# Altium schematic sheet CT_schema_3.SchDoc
size 578 x 363 mm
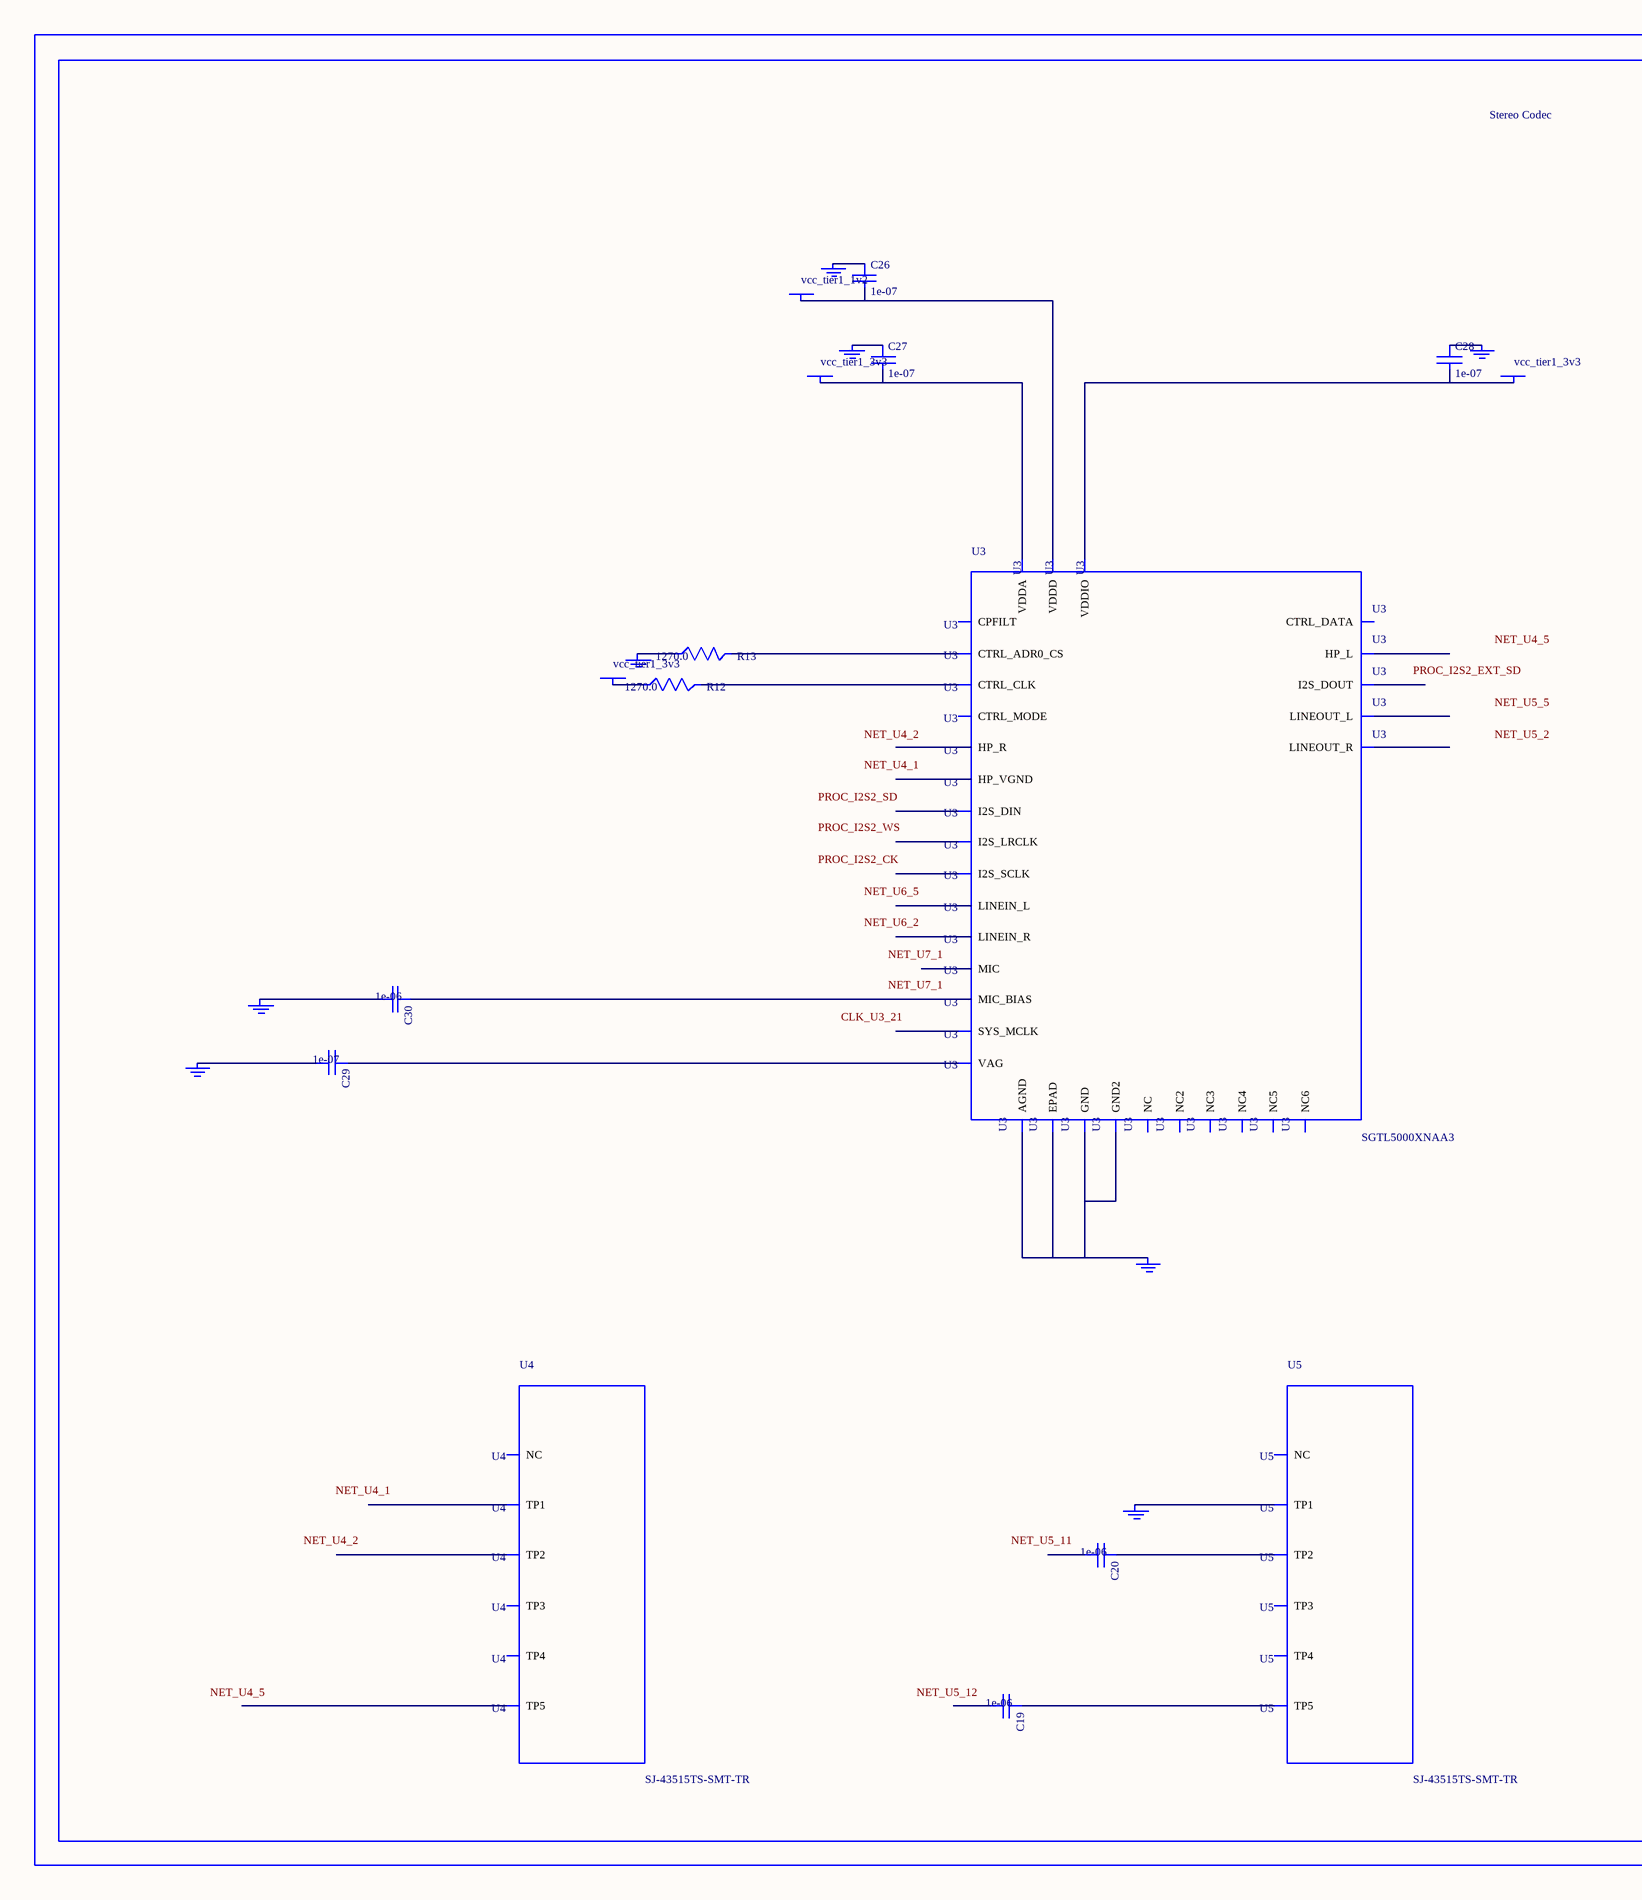
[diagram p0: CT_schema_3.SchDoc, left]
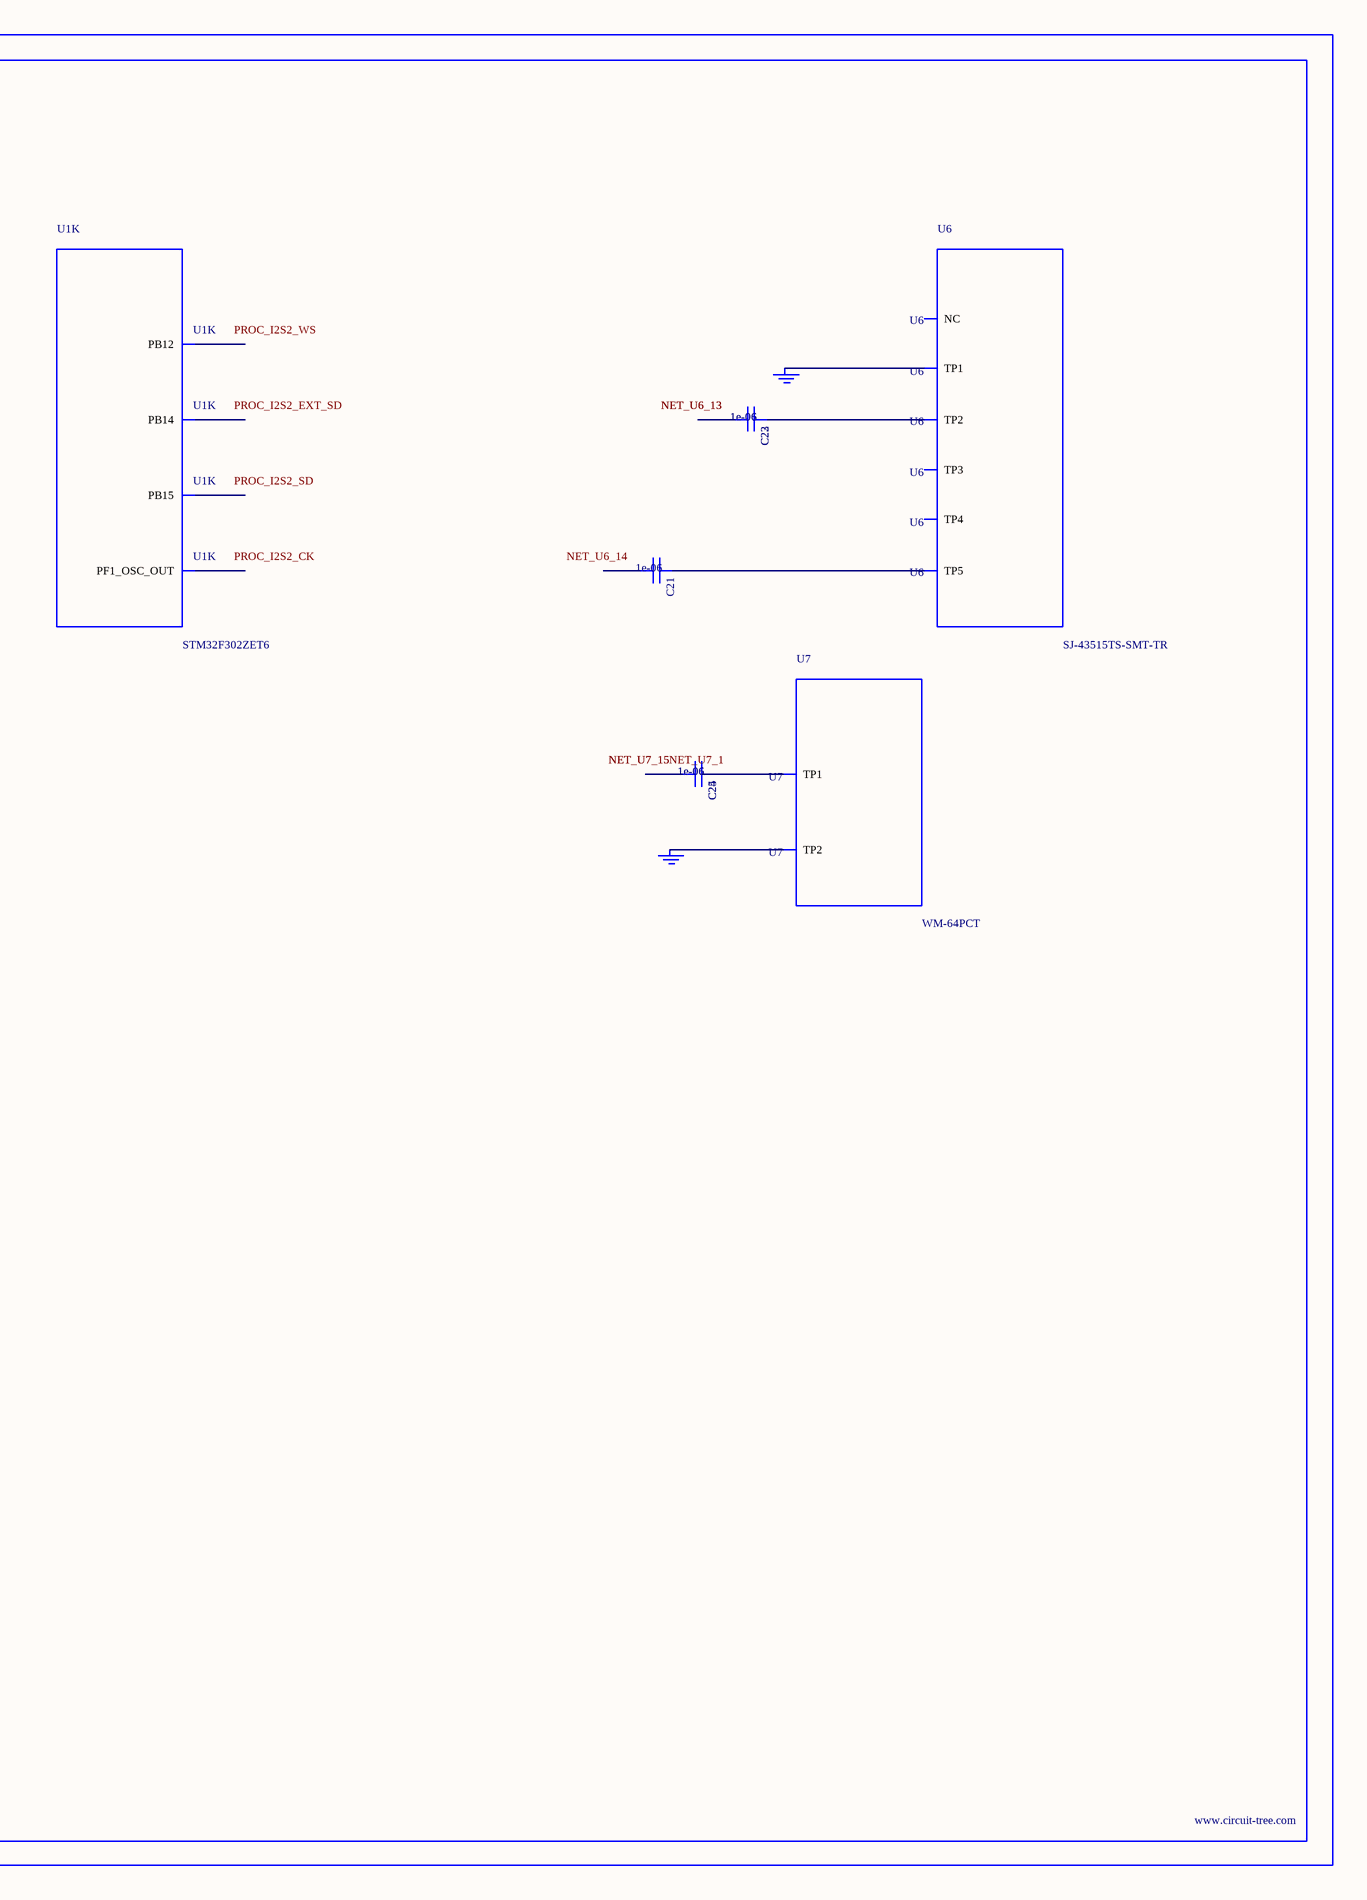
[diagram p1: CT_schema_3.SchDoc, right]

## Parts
BORDER2  (no value)
C19  1e-06  [C0603]
C20  1e-06  [C0603]
C21  1e-06  [C0603]
C22  1e-06  [C0603]
C23  1e-06  [C0603]
C24  1e-06  [C0603]
C25  1e-06  [C0603]
C26  1e-07  [C0402]
C27  1e-07  [C0402]
C28  1e-07  [C0402]
C29  1e-07  [C0402]
C30  1e-06  [C0603]
GND_INSTANCE_2_0  (no value)
GND_INSTANCE_2_1  (no value)
GND_INSTANCE_2_2  (no value)
GND_INSTANCE_2_3  (no value)
GND_INSTANCE_2_4  (no value)
GND_INSTANCE_2_5  (no value)
GND_INSTANCE_2_6  (no value)
GND_INSTANCE_2_7  (no value)
GND_INSTANCE_2_8  (no value)
GND_INSTANCE_2_9  (no value)
GND_INSTANCE_2_10  (no value)
POWER_INSTANCE_2_0  vcc_tier1_3v3
POWER_INSTANCE_2_1  vcc_tier1_3v3
POWER_INSTANCE_2_2  vcc_tier1_3v3
POWER_INSTANCE_2_3  vcc_tier1_1v2
R12  1270.0  [R0603]
R13  1270.0  [R0603]
U1  STM32F302ZET6  [LQFP144]  (part K of 12)
U3  SGTL5000XNAA3  [QFN-32]
U4  SJ-43515TS-SMT-TR  [SJ-43515TS-SMT-TR]
U5  SJ-43515TS-SMT-TR  [SJ-43515TS-SMT-TR]
U6  SJ-43515TS-SMT-TR  [SJ-43515TS-SMT-TR]
U7  WM-64PCT  [WM-64PC]

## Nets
NetC19_1: C19.1 U5.5(TP5)
NetC20_1: C20.1 U5.2(TP2)
NetC21_1: C21.1 U6.5(TP5)
NetC22_1: C22.1 C23.1 U6.2(TP2)
NetC22_2: C22.2 C23.2
NetC24_1: C24.1 C25.1 U7.1(TP1)
NetC24_2: C24.2 C25.2
NetC26_1: C26.1 GND_INSTANCE_2_5.0(GND)
NetC26_2: C26.2 POWER_INSTANCE_2_3.0(PWR) U3.30(VDDD)
NetC27_1: C27.1 GND_INSTANCE_2_1.0(GND)
NetC27_2: C27.2 POWER_INSTANCE_2_0.0(PWR) U3.5(VDDA)
NetC28_1: C28.1 GND_INSTANCE_2_4.0(GND)
NetC28_2: C28.2 POWER_INSTANCE_2_1.0(PWR) U3.20(VDDIO)
NetC29_1: C29.1 U3.10(VAG)
NetC29_2: C29.2 GND_INSTANCE_2_2.0(GND)
NetC30_1: C30.1 U3.16(MIC_BIAS)
NetC30_2: C30.2 GND_INSTANCE_2_3.0(GND)
NetGND_INSTANCE_2_0_0: GND_INSTANCE_2_0.0(GND) U3.1(GND) U3.3(GND2) U3.7(AGND) U3.EXP(EPAD)
NetGND_INSTANCE_2_6_0: GND_INSTANCE_2_6.0(GND) R13.1
NetGND_INSTANCE_2_7_0: GND_INSTANCE_2_7.0(GND) U5.1(TP1)
NetGND_INSTANCE_2_8_0: GND_INSTANCE_2_8.0(GND) GND_INSTANCE_2_9.0(GND) U6.1(TP1)
NetGND_INSTANCE_2_10_0: GND_INSTANCE_2_10.0(GND) U7.2(TP2)
NetPOWER_INSTANCE_2_2_0: POWER_INSTANCE_2_2.0(PWR) R12.1
NetR12_2: R12.2 U3.29(CTRL_CLK)
NetR13_2: R13.2 U3.31(CTRL_ADR0_CS)

Not connected (* = marked no-connect by the designer): C19 2; C20 2; C21 2; U1 24(PF1_OSC_OUT) 73(PB12) 75(PB14) 76(PB15); U3 2(HP_R) 4(HP_VGND) 6(HP_L) 8(NC) 9(NC2) 11(LINEOUT_R) 12(LINEOUT_L) 13(LINEIN_R) 14(LINEIN_L) 15(MIC) 17(NC3) 18(CPFILT) 19(NC4) 21(SYS_MCLK) 22(NC5) 23(I2S_LRCLK) 24(I2S_SCLK) 25(I2S_DOUT) 26(I2S_DIN) 27(CTRL_DATA) 28(NC6) 32(CTRL_MODE); U4 1(TP1) 2(TP2) 3(TP3) 4(TP4) 5(TP5) 6(NC); U5 3(TP3) 4(TP4) 6(NC); U6 3(TP3) 4(TP4) 6(NC)

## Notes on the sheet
- Labels drawn without touching a wire or pin: CLK_U3_21, NET_U4_1, NET_U4_2, NET_U4_5, NET_U5_2, NET_U5_5, NET_U5_11, NET_U5_12, NET_U6_2, NET_U6_5, NET_U6_14, NET_U7_1, PROC_I2S2_CK, PROC_I2S2_EXT_SD, PROC_I2S2_SD, PROC_I2S2_WS

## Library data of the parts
BORDER2 = BORDER_PAGE2
C19-C25 C30 = C0603C105K3RACTU
C26-C29 = C0402C104K3RACTU
GND_INSTANCE_2_0-GND_INSTANCE_2_10 = GND
POWER_INSTANCE_2_0-POWER_INSTANCE_2_3 = PWR
R12 R13 = RC0603FR-071K27L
